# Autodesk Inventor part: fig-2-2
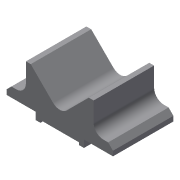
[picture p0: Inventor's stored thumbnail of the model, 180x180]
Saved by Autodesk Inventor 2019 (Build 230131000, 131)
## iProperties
Shininess: 64.0
Length Units: 11269
Angle Units: 11279
Time Units: 11290
Mass Units: 11283
Length Display Precision: 3
Angle Display Precision: 2
Compacted: True
Part Number: fig-2-2
Document SubType Name: Modeling
Created: 2002-11
Designer: deepak
Density: 1 g/cm^3
Material: Generic
Appearance: Default
Density: 0.0
Volumn: 0.0
Area: 0.0
PropertySet Name: Model Information
Control State: 0
Master: False
Checked Out: False
Author: CADCIM
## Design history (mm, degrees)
sketch "Sketch1"
  geometry: L1 (0, 0)-(-3, 3); L2 (-3, 3)-(-3.5, 3); L3 (-3.5, 3)-(-3.5, 0); L4 (-3.5, 0)-(-5.5, 0); L5 (-5.5, 0)-(-5.5, -1); L6 (-5.5, -1)-(-2.5, -1); L7 (-2.5, -1)-(-2.5, -1.75); L8 (-2.5, -1.75)-(-2, -1.75); L9 (-2, -1.75)-(-2, -1.5); L10 (-2, -1.5)-(2, -1.5); L11 (2, -1.5)-(2, -1.75); L12 (2, -1.75)-(2.5, -1.75); L13 (2.5, -1.75)-(2.5, -1); L14 (2.5, -1)-(5.5, -1); L15 (5.5, -1)-(5.5, 0); L16 (5.5, 0)-(3.5, 0); L17 (3.5, 0)-(3.5, 3); L18 (3.5, 3)-(3, 3); L19 (3, 3)-(0, 0)
  constraints: 38 end point, 17 perpendicular, 1 horizontal
extrude "Extrusion1" new body sketch "Sketch1" distance "d0" = 6.25; taper "d1" = 0 deg
fillet "Fillet1" dims "d2" = 1
chamfer "Chamfer1" distance "d3" = 0.5; stored, may be unused: second distance "d4" = 2, angle "d5" = 45 deg
body "Solid1"
